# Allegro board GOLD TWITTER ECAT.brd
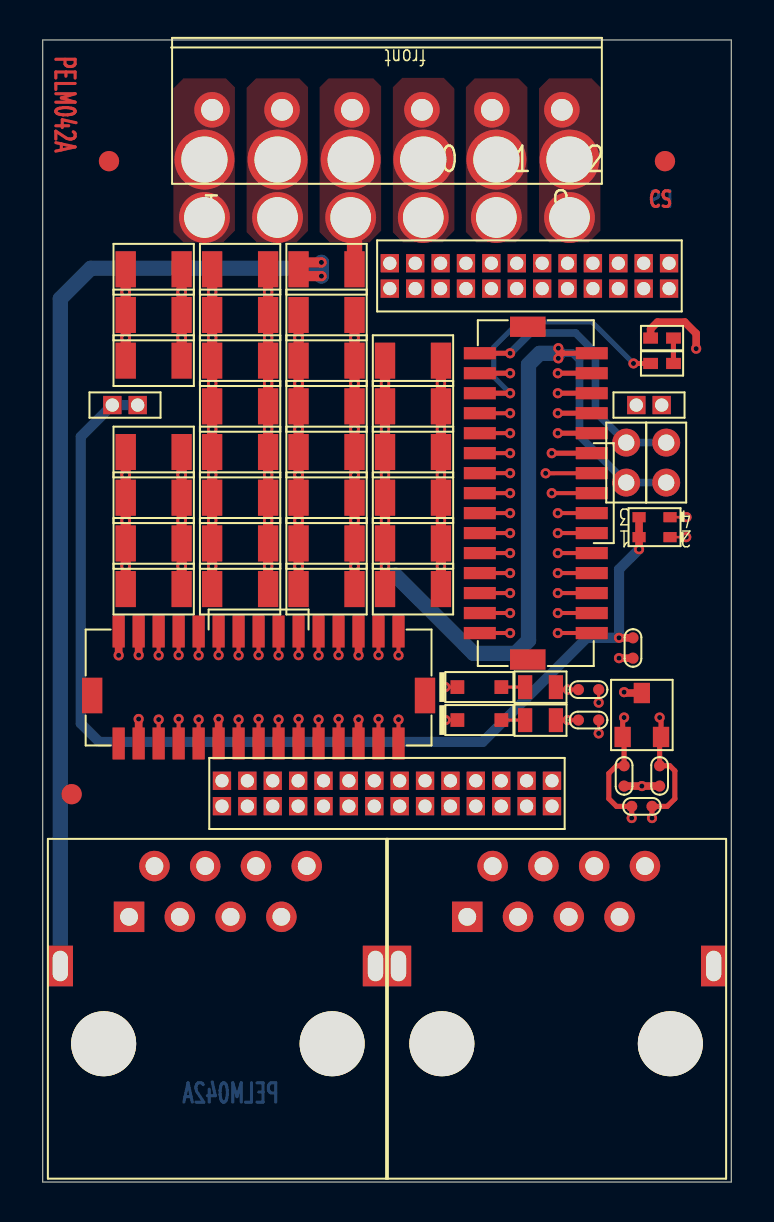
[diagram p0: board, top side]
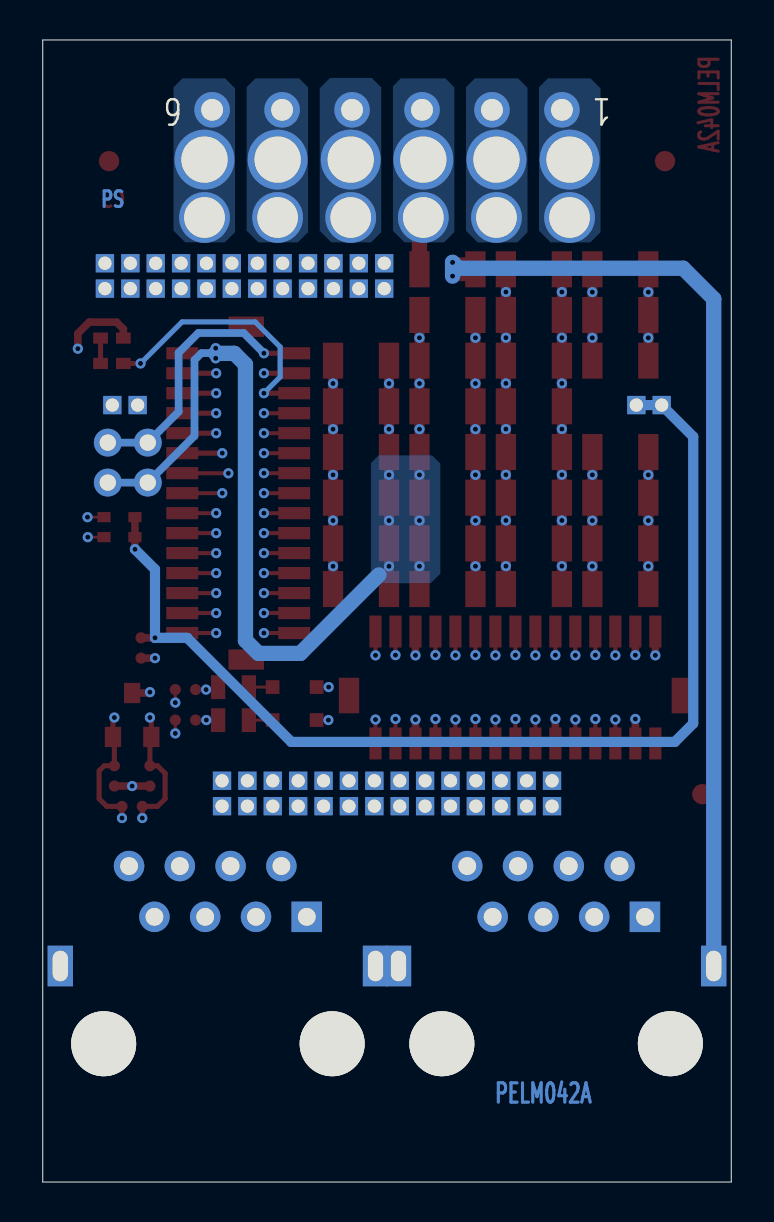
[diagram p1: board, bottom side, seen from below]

Outline 34.44 x 57.14 mm; copper layers: TOP, L2, L3, L4, L5, BOTTOM. Coordinates in mm from the lower left corner of the outline.
Outline path: 0,57.14 34.44,57.14 34.44,0 0,0 0,57.14

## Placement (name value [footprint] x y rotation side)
C1  1uF  [1206]  5.55 45.67 0 top
C2  1uF  [1206]  9.87 45.67 180 top
C4  1uF  [1206]  5.55 43.38 0 top
C5  1uF  [1206]  9.87 43.38 180 top
C6  1uF  [1206]  14.2 43.38 0 top
C7  1uF  [1206]  5.55 41.1 0 top
C8  1uF  [1206]  9.87 41.1 180 top
C9  1uF  [1206]  14.2 41.1 0 top
C10  1uF  [1206]  14.2 38.81 0 top
C11  1uF  [1206]  9.87 38.81 180 top
C12  1uF  [1206]  5.55 36.53 0 top
C13  1uF  [1206]  9.87 36.53 180 top
C14  1uF  [1206]  14.2 36.53 0 top
C15  1uF  [1206]  18.52 41.1 180 top
C16  1uF  [1206]  18.52 38.81 180 top
C17  1uF  [1206]  18.52 36.53 180 top
C18  1uF  [1206]  5.55 34.24 0 top
C19  1uF  [1206]  9.87 34.24 180 top
C20  1uF  [1206]  14.2 34.24 0 top
C21  1uF  [1206]  18.52 34.24 180 top
C22  1uF  [1206]  5.55 31.95 0 top
C23  1uF  [1206]  9.87 31.95 180 top
C24  1uF  [1206]  14.2 31.95 0 top
C25  1uF  [1206]  18.52 31.95 180 top
C26  1uF  [1206]  18.52 29.67 180 top
C27  1uF  [1206]  14.2 29.67 0 top
C28  1uF  [1206]  9.87 29.67 180 top
C29  1uF  [1206]  5.55 29.67 0 top
C32  1uF  [0402]  29.53 26.72 270 top
C33  33pF  [0402]  29.08 20.32 270 top
C34  33pF  [0402]  30.86 20.32 270 top
D1  LDR/G  [LED06]  30.61 32.77 180 top
D5  BAS521  [SOD523]  30.98 40.96 180 top
D6  BAS521  [SOD523]  30.98 42.23 0 top
D7  NUP2105L  [SOT23]  29.97 23.37 180 top
D8  DZ6.2v  [SOD323]  21.84 23.11 0 top
D9  DZ6.2v  [SOD323]  21.84 24.77 0 top
FD1  -  [FD1]  1.45 19.41 0 top
FD2  -  [FD1]  31.13 51.08 0 top
FD3  -  [FD1]  3.31 51.08 0 top
H1  H8  [H08]  8.09 48.26 0 top
H2  H8  [H08]  11.75 48.26 0 top
H3  H8  [H08]  15.41 48.26 0 top
H4  H8  [H08]  19.04 48.26 0 top
H5  H8  [H08]  22.69 48.26 0 top
H6  H8  [H08]  26.35 48.26 0 top
H7  -  [H52]  8.09 51.16 0 top
H8  -  [H52]  11.75 51.16 0 top
H9  -  [H52]  15.41 51.16 0 top
H10  -  [H52]  19.04 51.16 0 top
H11  -  [H52]  22.69 51.16 0 top
H12  -  [H52]  26.35 51.16 0 top
J2  J  [HEADER194]  31.33 45.97 270 top
J3  J  [HEADER245]  25.48 20.08 270 top
J7  J  [HEADER52A]  31.19 37 270 top
J8  J  [HEADER278A]  29.7 38.88 0 top
J9  J  [HEADER278A]  3.48 38.88 0 top
J10  J  [HEADER283]  24.67 34.47 180 top
J11  J  [HEADER283]  10.8 24.74 270 top
J12  J  [HEADER52]  29.19 37 270 top
J13  J  [CON22]  4.32 13.27 180 top
J15  J  [CON22]  21.24 13.27 180 top
J16  J  [TB54]  8.47 53.65 180 top
NOREF  -  []  0 57.14 0 top
NOREF#2  -  []  0 0 90 top
NOREF#3  -  []  -39.4 83.35 0 top
NOREF#4  -  []  0 0 90 top
NOREF#5  -  []  0 0 0 top
R12  0R  [0402]  27.3 23.11 0 top
R13  3.74K  [0603]  24.9 23.11 180 top
R14  0R  [0402]  27.3 24.64 0 top
R15  0R  [1206]  14.2 45.67 180 top
R16  Demo  [0402]  29.97 18.8 0 top
R17  3.74K  [0603]  24.9 24.76 180 top

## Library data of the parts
C1 C2 C4-C29 = C1uF_200v_X7R_1206
C32 = C1uF_10v_X5R_0402
C33 C34 = C33pF_50v_NPO_0402
D1 = LED_BICOLOR_LED06
D5 D6 = BAS521HT1_SOD523
D7 = NUP2105L_SOT23
D8 D9 = MM3Z6V2_SOD323
FD1-FD3 = FIDUCIAL1_FD1
H1-H6 = HOLE08_H08
H7-H12 = HOLE52_H52
J2 = HEADER2x12PF1.27_4.3_HEADER194
J3 = HEADER2x14PF1.27_4.3_HEADER245
J7 = HEADER52A_FP12
J8 J9 = HEADER2P1.27mmHEADER278A
J10 J11 = HEADER2x15P1mm_HEADER283
J12 = HEADER2PF2mm_4.3mm_HEADER52
J13 J15 = CON1PORT8P_CON22
J16 = TB6P3.5mm_TB54
R12 R14 = 0R_0402
R13 R17 = 3.74K1%_0603
R15 = 0R_1206
R16 = RES0402_DEMO

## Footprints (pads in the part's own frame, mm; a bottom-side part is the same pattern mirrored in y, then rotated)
0402
  round 0.559 smd: 1(-0.508,0) 2(0.508,0)
0603
  rect 0.711x1.194 smd: 1(-0.77,0) 2(0.77,0)
1206
  rect 1.016x1.803 smd: 1(-1.4,0) 2(1.4,0)
CON22
  round 3.251 hole 3.302 unplated: (-10.16,6.35) (1.27,6.35)
  rect 1.524x1.524 hole 0.889: 1(0,0)
  round 1.524 hole 0.889: 2(-1.27,-2.54) 3(-2.54,0) 4(-3.81,-2.54) 5(-5.08,0) 6(-6.35,-2.54) 7(-7.62,0) 8(-8.89,-2.54)
  rect 1.27x2.032 hole 0.762x1.524: 9(3.44,2.46) 10(-12.33,2.46)
FD1
  round 1.016 smd: 1(0,0)
H08
  round 2.54 hole 2.032: 1(0,0)
H52
  round 2.997 hole 2.311: 1(0,0)
HEADER52
  round 1.397 hole 0.813: 1(0,0) 2(2,0)
HEADER52A
  round 1.397 hole 0.813: 1(0,0) 2(2,0)
HEADER194
  rect 0.914x0.914 hole 0.66: 1(0,0) 2(1.27,0) 3(0,-1.27) 4(1.27,-1.27) 5(0,-2.54) 6(1.27,-2.54) 7(0,-3.81) 8(1.27,-3.81) 9(0,-5.08) 10(1.27,-5.08) 11(0,-6.35) 12(1.27,-6.35) 13(0,-7.62) 14(1.27,-7.62) 15(0,-8.89) 16(1.27,-8.89) 17(0,-10.16) 18(1.27,-10.16) 19(0,-11.43) 20(1.27,-11.43) 21(0,-12.7) 22(1.27,-12.7) 23(0,-13.97) 24(1.27,-13.97)
HEADER245
  rect 0.914x0.914 hole 0.66: 1(0,0) 2(1.27,0) 3(0,-1.27) 4(1.27,-1.27) 5(0,-2.54) 6(1.27,-2.54) 7(0,-3.81) 8(1.27,-3.81) 9(0,-5.08) 10(1.27,-5.08) 11(0,-6.35) 12(1.27,-6.35) 13(0,-7.62) 14(1.27,-7.62) 15(0,-8.89) 16(1.27,-8.89) 17(0,-10.16) 18(1.27,-10.16) 19(0,-11.43) 20(1.27,-11.43) 21(0,-12.7) 22(1.27,-12.7) 23(0,-13.97) 24(1.27,-13.97) 25(0,-15.24) 26(1.27,-15.24) 27(0,-16.51) 28(1.27,-16.51)
HEADER278A
  rect 0.914x0.914 hole 0.66: 1(0,0) 2(1.27,0)
HEADER283
  rect 1.778x1.016 smd: (0.4,8.325) (0.4,-8.325)
  rect 1.6x0.61 smd: 1(-2.8,7) 2(2.8,7) 3(-2.8,6) 4(2.8,6) 5(-2.8,5) 6(2.8,5) 7(-2.8,4) 8(2.8,4) 9(-2.8,3) 10(2.8,3) 11(-2.8,2) 12(2.8,2) 13(-2.8,1) 14(2.8,1) 15(-2.8,0) 16(2.8,0) 17(-2.8,-1) 18(2.8,-1) 19(-2.8,-2) 20(2.8,-2) 21(-2.8,-3) 22(2.8,-3) 23(-2.8,-4) 24(2.8,-4) 25(-2.8,-5) 26(2.8,-5) 27(-2.8,-6) 28(2.8,-6) 29(-2.8,-7) 30(2.8,-7)
LED06
  rect 0.66x0.508 smd: 1(0.775,0.5) 2(-0.775,0.5) 3(0.775,-0.5) 4(-0.775,-0.5)
SOD323
  rect 0.686x0.686 smd: 1(-1.1,0) 2(1.1,0)
SOD523
  rect 0.737x0.559 smd: 1(-0.572,0) 2(0.572,0)
SOT23
  rect 0.813x1.016 smd: 1(0.96,1.1) 2(-0.96,1.1) 3(0,-1.1)
TB54
  round 1.778 hole 1.09: 1(0,0) 2(-3.5,0) 3(-7,0) 4(-10.5,0) 5(-14,0) 6(-17.5,0)

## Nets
3.3V: C32.1 D1.1(ANODE_R) D1.3(ANODE_G) D6.1(K) J9.1 J9.2
+5VE: D5.2(A) J2.19 J10.19 J10.26
GND: C32.2 D7.3(PIN3) J2.21 J2.23 J3.7 J3.8 J3.21 J3.22 J10.21 J10.23 J10.25 J10.27 J10.28 J11.5 J11.6 J11.20 J11.27 J11.28 J11.29 J13.3 J13.7 J15.3 J15.7
GND_POWER: C33.2 C34.2 J13.6 J13.9 J13.10 J15.6 J15.9 J15.10 R15.2
ANALOG1+: J3.9 J11.7
ANALOG1-: J3.10 J11.8
AUX_H: J7.1 J10.30 J12.1
CAN_H: C33.1 D7.1(PIN1) J3.1 J13.1 J15.1 R16.1
CAN_L: C34.1 D7.2(PIN2) J3.2 J13.2 J15.2 R16.2
ENCA_A+_ABS_C+: J2.1 J10.1
ENCA_A-_ABS_C-: J2.3 J10.3
ENCA_B+_ABS_D+: J2.5 J10.5
ENCA_B-_ABS_D-: J2.7 J10.7
ENCA_INDEX+: J2.9 J10.9
ENCA_INDEX-: J2.11 J10.11
ENCB_A+: J2.4 J10.4
ENCB_A-: J2.2 J10.2
ENCB_B+: J2.8 J10.8
ENCB_B-: J2.6 J10.6
ENCB_INDEX+: J2.12 J10.12
ENCB_INDEX-: J2.10 J10.10
ENCC_A_O+: J2.16 J10.16
ENCC_A_O-: J2.14 J10.14
ENCC_B_O+: J2.20 J10.20
ENCC_B_O-: J2.18 J10.18
ENCC_INDEX_O+: J2.24 J10.24
ENCC_INDEX_O-: J2.22 J10.22
GPIO5_ANALOG_IN: J3.11 J11.9
GPIO8_PAL_RS232_RX: J3.6 J11.4
GPIO9_PAL_RS232_TX: J3.5 J11.3
HA: J2.13 J10.13
HB: J2.15 J10.15
HC: J2.17 J10.17
IN1: J3.28 J11.26
IN2: J3.27 J11.25
IN3: J3.26 J11.24
IN4: J3.25 J11.23
IN5: J3.24 J11.22
IN6: J3.23 J11.21
LED1: D1.2(CATHODE_R) J3.15 J11.13
LED2: D1.4(CATHODE_G) J3.16 J11.14
M1: H4.1(H) H10.1(H) J16.4
M2: H5.1(H) H11.1(H) J16.5
M3: H6.1(H) H12.1(H) J16.6
OUT1_E: J3.20 J11.18
OUT2_E: J3.18 J11.16
OUT3_E: J3.19 J11.17
OUT4_E: J3.17 J11.15
PE: H3.1(H) H9.1(H) J16.3 R15.1
PR: C1.2 C2.2 C4.2 C5.2 C6.2 C7.2 C8.2 C9.2 C10.2 C11.2 C12.2 C13.2 C14.2 C15.2 C16.2 C17.2 C18.2 C19.2 C20.2 C21.2 C22.2 C23.2 C24.2 C25.2 C26.2 C27.2 C28.2 C29.2 H1.1(H) H7.1(H) J7.2 J10.29 J12.2 J16.1
RS232_RX: J3.4 J11.2
RS232_TX: J3.3 J11.1
STO1: J3.12 R12.1 R13.1
STO1_IN: D8.1(K) J11.10 R12.2
STO2: J3.14 R14.1 R17.1
STO2_IN: D9.1(K) J11.12 R14.2
STO_RET: J3.13 J11.11
VP+: C1.1 C2.1 C4.1 C5.1 C6.1 C7.1 C8.1 C9.1 C10.1 C11.1 C12.1 C13.1 C14.1 C15.1 C16.1 C17.1 C18.1 C19.1 C20.1 C21.1 C22.1 C23.1 C24.1 C25.1 C26.1 C27.1 C28.1 C29.1 H2.1(H) H8.1(H) J16.2
N14985989: D5.1(K) D6.2(A)
N16792816: D8.2(A) R13.2
N16792834: D9.2(A) R17.2

Pads without a net: FD1 1; FD2 1; FD3 1; J8 1 2; J11 19 30; J13 4 5 8; J15 4 5 8

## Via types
v1: diameter 0.508, hole 0.254, TOP to BOTTOM, 127 vias

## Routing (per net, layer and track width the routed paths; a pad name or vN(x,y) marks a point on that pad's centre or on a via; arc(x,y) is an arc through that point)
3.3V: length 58.3
  TOP w0.381: v1(29.83,31.66) D1.1 D1.3 ; v1(32.69,41.7) 32.69,42.46 32.12,43.03 30.75,43.03 30.41,42.68 D6.1 ; C32.1 v1(28.83,27.23)
  BOTTOM w0.508: v1(29.83,31.66) 28.83,30.66 v1(28.83,27.23) 27.22,27.23 22.01,22.02 2.83,22.02 1.9,22.94 1.9,37.29 3.48,38.87 J9.1 J9.2
+5VE: length 15.4
  TOP w0.254: J10.19 v1(25.46,36.47) ; D5.2 v1(29.55,40.96) ; J10.26 v1(23.38,39.47)
  BOTTOM w0.254: v1(29.55,40.96) 27.48,43.03 23.82,43.03 22.57,41.78 22.57,40.28 v1(23.38,39.47)
GND: length 17.1
  TOP w0.254: J10.23 v1(25.77,38.47) ; J10.28 v1(23.38,40.47) ; J10.21 v1(25.77,37.47) ; J10.25 v1(25.77,39.47) ; J10.27 v1(25.77,40.47)
  TOP w0.381: J11.20 v1(8.8,23.17) ; J11.5 v1(15.8,26.35) ; C32.2 v1(28.83,26.21) ; J11.28 v1(4.8,23.17) ; J11.6 v1(15.8,23.14) ; J11.29 v1(3.8,26.35) ; D7.3 29.13,24.47 v1(29.08,24.51) ; J11.27 v1(4.8,26.36)
GND_POWER: length 57.6
  TOP w0.381: C33.2 v1(29.97,19.81) C34.2
  TOP w0.508: v1(13.94,46.01) 13.14,46.01 R15.2 13.14,45.33 v1(13.94,45.33)
  L4 w0.762: v1(29.97,19.81) 29.41,19.81 27.59,17.99 J15.6
  BOTTOM w0.762: J13.9 0.88,44.19 2.41,45.72 13.65,45.72 v1(13.94,46.01) v1(13.94,45.33)
ANALOG1+: length 10.1
  TOP w0.203: J11.7 v1(14.8,26.36)
  L3 w0.178: 17.3,23.86 17.3,22.89
  L3 w0.203: J3.9 20.4,20.29 18.33,22.35 17.84,22.35 17.3,22.89 ; v1(14.8,26.36) 17.3,23.86
ANALOG1-: length 9.5
  TOP w0.203: J11.8 v1(14.8,23.17)
  L4 w0.127: 19.76,20.48 19.76,19.44
  L4 w0.203: 19.76,19.44 J3.10 ; 19.76,20.48 18.85,21.39 16.14,21.39 14.8,22.72 v1(14.8,23.17)
AUX_H: length 13.7
  TOP w0.254: J10.30 v1(23.38,41.47)
  BOTTOM w0.381: J7.1 J12.1 27.65,38.54 27.65,41.49 26.66,42.48 24.39,42.48 v1(23.38,41.47)
CAN_H: length 46.3
  TOP w0.254: v1(29.46,18.21) R16.1 28.7,18.8 28.32,19.18 28.32,20.45 28.7,20.83 C33.1 29.08,22.2 D7.1 29.01,23.17 v1(29.08,23.24)
  L2 w0.254: J13.1 5.23,12.36 5.23,11.87 5.8,11.3 12.45,11.3 15.39,14.24 20.26,14.24 21.23,13.27 J15.1
  L3 w0.152: J3.1 25.97,19.58 27.43,19.58 27.71,19.85 27.71,21.1 28.43,21.83 29.59,21.83 29.85,22.09 29.85,22.94 29.54,23.24 v1(29.08,23.24)
  L3 w0.254: J15.1 21.24,16.23 22.61,17.6 28.85,17.6 v1(29.46,18.21)
CAN_L: length 47.1
  TOP w0.254: v1(30.48,18.21) R16.2 31.24,18.8 31.62,19.18 31.62,20.57 31.37,20.83 C34.1 30.86,22.2 D7.2 30.93,23.17 v1(30.86,23.24)
  L2 w0.254: J13.2 5.69,15.71 5.69,12.1 6.03,11.76 12.29,11.76 15.15,14.63 21.32,14.63 22.5,15.81 J15.2
  L3 w0.152: v1(30.86,23.24) 30.41,23.24 30.13,22.96 30.13,21.94 29.7,21.51 28.56,21.51 28,20.96 28,19.7 27.6,19.3 25.97,19.3 J3.2
  L3 w0.254: J15.2 22.51,16.72 22.96,17.17 29.44,17.17 v1(30.48,18.21)
ENCA_A+_ABS_C+: length 23.2
  TOP w0.203: J10.1 v1(25.77,27.47)
  L3 w0.127: 30.7,45.34 30.7,44.22
  L3 w0.152: 30.7,44.22 30.24,43.77 29.49,43.77 28.19,42.47 28.19,29.5 26.16,27.47 v1(25.77,27.47) ; J2.1 30.7,45.34
ENCA_A-_ABS_C-: length 21.2
  TOP w0.203: J10.3 v1(25.77,28.47)
  L3 w0.127: 29.43,44.31 29.43,45.34
  L3 w0.152: 29.43,45.34 J2.3 ; 29.43,44.31 27.85,42.73 27.85,30.15 26.16,28.47 v1(25.77,28.47)
ENCA_B+_ABS_D+: length 19.7
  TOP w0.203: J10.5 v1(25.77,29.47)
  L3 w0.127: 28.16,45.34 28.16,44.22
  L3 w0.152: J2.5 28.16,45.34 ; v1(25.77,29.47) 26.18,29.47 27.51,30.8 27.51,43.57 28.16,44.22
ENCA_B-_ABS_D-: length 18.4
  TOP w0.203: J10.7 v1(25.77,30.47)
  L3 w0.127: 26.89,45.34 26.89,44.12
  L3 w0.152: 26.89,44.12 27.18,43.83 27.18,31.46 26.18,30.47 v1(25.77,30.47) ; J2.7 26.89,45.34
ENCA_INDEX+: length 17.6
  TOP w0.203: J10.9 v1(25.77,31.47)
  L3 w0.127: 25.62,44.25 25.62,45.34
  L3 w0.152: 25.62,44.25 26.84,43.03 26.84,32.14 26.17,31.47 v1(25.77,31.47) ; 25.62,45.34 J2.9
ENCA_INDEX-: length 16.7
  TOP w0.203: J10.11 v1(25.77,32.47)
  L3 w0.127: 24.35,45.34 24.35,44.36
  L3 w0.152: 24.35,44.36 26.5,42.2 26.5,33.05 25.92,32.47 v1(25.77,32.47) ; J2.11 24.35,45.34
ENCB_A+: length 21.9
  TOP w0.203: J10.4 v1(23.38,28.47)
  L4 w0.152: v1(23.38,28.47) 23.38,28.47 23.88,28.97 26.17,28.97 27.67,30.48 27.67,42.24 30.06,44.64 J2.4
ENCB_A-: length 23.9
  TOP w0.203: J10.2 v1(23.38,27.47)
  L4 w0.152: v1(23.38,27.47) 23.88,27.96 26.15,27.96 28.02,29.84 28.02,42.03 29.46,43.47 30.45,43.47 31.33,44.36 J2.2
ENCB_B+: length 18.8
  TOP w0.203: J10.8 v1(23.38,30.47)
  L4 w0.152: v1(23.38,30.47) 23.38,30.47 23.89,30.98 26.24,30.98 27.01,31.75 27.01,44.19 J2.8
ENCB_B-: length 20.3
  TOP w0.203: J10.6 v1(23.38,29.47)
  L4 w0.152: J2.6 28.79,44.09 27.34,42.63 27.34,31.19 26.11,29.96 23.87,29.96 v1(23.38,29.47)
ENCB_INDEX+: length 16.8
  TOP w0.203: J10.12 v1(23.38,32.47)
  L4 w0.152: J2.12 24.98,44.1 26.32,42.76 26.32,33.26 26.02,32.97 23.87,32.97 23.38,32.47 v1(23.38,32.47)
ENCB_INDEX-: length 17.6
  TOP w0.203: J10.10 v1(23.38,31.47)
  L4 w0.152: v1(23.38,31.47) 23.88,31.97 26.04,31.97 26.67,32.6 26.67,43.73 26.25,44.16 J2.10
ENCC_A_O+: length 13.4
  TOP w0.203: J10.16 v1(23.38,34.47)
  L3 w0.152: v1(23.38,34.47) 23.89,34.97 23.89,35.42 24.56,36.09 24.56,37.03 24.89,37.37 24.89,42.25 J2.16
ENCC_A_O-: length 14.1
  TOP w0.203: J10.14 v1(23.38,33.47)
  L3 w0.152: J2.14 23.71,44.22 25.23,42.7 25.23,37.1 24.93,36.8 24.93,35.93 24.21,35.21 24.21,34.29 v1(23.38,33.47)
ENCC_B_O+: length 12.8
  TOP w0.203: J10.20 v1(23.38,36.47)
  L3 w0.152: J2.20 19.9,44.62 21.2,43.32 22.74,43.32 24.22,41.84 24.22,37.67 23.87,37.33 23.87,36.96 v1(23.38,36.47)
ENCC_B_O-: length 13.2
  TOP w0.203: J10.18 v1(23.38,35.47)
  L3 w0.152: J2.18 21.17,44.37 21.72,43.82 22.77,43.82 24.55,42.04 24.55,37.48 24.18,37.11 24.18,36.27 v1(23.38,35.47)
ENCC_INDEX_O+: length 11.9
  TOP w0.203: J10.24 v1(23.38,38.47)
  L3 w0.152: J2.24 18.35,43.72 19.93,43.72 20.93,42.72 22.18,42.72 22.87,42.03 22.87,38.98 v1(23.38,38.47)
ENCC_INDEX_O-: length 12.4
  TOP w0.203: J10.22 v1(23.38,37.47)
  L3 w0.152: v1(23.38,37.47) 23.89,37.98 23.89,41.65 22.5,43.04 21.05,43.04 20.08,44.01 19.33,44.01 19.19,44.14 19.19,44.14 J2.22
GPIO5_ANALOG_IN: length 9.7
  TOP w0.203: J11.9 v1(13.8,26.35)
  L3 w0.178: 16.3,22.92 16.3,23.85
  L3 w0.203: J3.11 19.13,20.09 16.3,22.92 ; 16.3,23.85 v1(13.8,26.35)
GPIO8_PAL_RS232_RX: length 9.9
  TOP w0.203: J11.4 v1(16.8,23.17)
  L4 w0.127: 22.3,19.44 22.3,20.52
  L4 w0.203: J3.6 22.3,19.44 ; 22.3,20.52 22.04,20.79 20.39,20.79 19.08,22.1 17.62,22.1 16.8,22.92 v1(16.8,23.17)
GPIO9_PAL_RS232_TX: length 10.9
  TOP w0.203: J11.3 v1(16.8,26.36)
  L3 w0.203: v1(16.8,26.36) 18.51,24.65 18.51,23.2 20.67,21.05 22.26,21.05 22.94,20.37 J3.5
HA: length 16
  TOP w0.203: J10.13 v1(25.77,33.47)
  L4 w0.127: 23.08,45.34 23.08,43.79
  L4 w0.152: v1(25.77,33.47) 25.77,33.47 25.98,33.67 25.98,36.72 25.72,36.98 25.31,36.98 25.07,37.22 25.07,41.8 23.08,43.79 ; J2.13 23.08,45.34
HB: length 15.8
  TOP w0.203: J10.15 v1(25.46,34.47)
  L4 w0.127: 21.81,44.29 21.81,45.34
  L4 w0.152: 21.81,44.29 22.09,44.01 22.32,44.01 24.72,41.61 24.72,36.29 25.02,35.98 25.46,35.98 25.66,35.78 25.66,34.71 v1(25.46,34.47) ; 21.81,45.34 J2.15
HC: length 15.6
  TOP w0.203: J10.17 v1(25.16,35.46)
  L4 w0.127: 20.54,44.3 20.54,45.34
  L4 w0.152: 20.54,44.3 21.25,43.59 22.21,43.59 24.38,41.41 24.38,36.08 25,35.46 v1(25.16,35.46) ; 20.54,45.34 J2.17
IN1: length 6.8
  TOP w0.203: J11.26 v1(5.8,23.14)
  L4 w0.127: 8.33,19.44 8.33,19.44
  L4 w0.203: v1(5.8,23.14) 5.8,21.97 8.33,19.44 ; 8.33,19.44 J3.28
IN2: length 8.8
  TOP w0.203: J11.25 v1(5.8,26.35)
  L3 w0.178: 8.3,22.64 8.3,23.85
  L3 w0.203: J3.27 8.97,21.97 8.3,22.64 ; 8.3,23.85 v1(5.8,26.35)
IN3: length 7.4
  TOP w0.203: J11.24 v1(6.8,23.17)
  L4 w0.127: 9.6,20.52 9.6,19.44
  L4 w0.203: v1(6.8,23.17) 6.8,22.6 8.43,20.97 9.15,20.97 9.6,20.52 ; 9.6,19.44 J3.26
IN4: length 8.9
  TOP w0.203: J11.23 v1(6.8,26.36)
  L3 w0.178: 9.3,22.66 9.3,23.86
  L3 w0.203: 9.3,22.66 10.24,21.72 J3.25 ; 9.3,23.86 v1(6.8,26.36)
IN5: length 7.7
  TOP w0.203: J11.22 v1(7.8,23.14)
  L4 w0.127: 10.87,20.52 10.87,19.44
  L4 w0.203: 10.87,19.44 J3.24 ; 10.87,20.52 9.71,21.68 8.59,21.68 7.8,22.48 v1(7.8,23.14)
IN6: length 9
  TOP w0.203: J11.21 v1(7.8,26.35)
  L3 w0.178: 10.3,22.86 10.3,23.85
  L3 w0.203: 10.3,22.86 11.51,21.65 J3.23 ; 10.3,23.85 v1(7.8,26.35)
LED1: length 33.5
  TOP w0.127: D1.2 v1(32.19,32.27)
  TOP w0.203: J11.13 v1(11.8,26.35)
  L2 w0.152: v1(32.19,32.27) 32.19,31.85 26.84,26.5 20.27,26.5 18.63,24.86 18.63,21.47 18.4,21.24 17.35,21.24 16.92,20.81 16.92,20.41 16.59,20.08 J3.15
  L3 w0.178: 14.3,22.21 14.3,23.85
  L3 w0.203: 14.3,22.21 16.44,20.08 J3.15 ; 14.3,23.85 v1(11.8,26.35)
LED2: length 35.3
  TOP w0.127: D1.4 v1(32.21,33.27)
  TOP w0.203: J11.14 v1(11.8,23.14)
  L2 w0.127: 17.22,20.62 17.22,19.44
  L2 w0.152: 17.22,20.62 17.55,20.95 18.63,20.95 18.93,21.25 18.93,24.66 20.47,26.2 26.97,26.2 30.6,29.82 30.6,29.83 32.75,31.97 32.75,32.73 v1(32.21,33.27) ; 17.22,19.44 J3.16
  L4 w0.127: 15.95,21.02 15.95,19.44
  L4 w0.203: 15.95,21.02 14.58,22.4 12.54,22.4 v1(11.8,23.14) ; 15.95,19.44 J3.16
Net_10: length 1.2
  TOP w0.203: 8.8,27.54 v1(8.8,26.36)
OUT1_E: length 8.1
  TOP w0.203: J11.18 v1(9.8,23.14)
  L4 w0.127: 13.41,19.44 13.41,20.45
  L4 w0.203: v1(9.8,23.14) 9.8,22.76 11.53,21.03 12.83,21.03 13.41,20.45 ; J3.20 13.41,19.44
OUT2_E: length 8.3
  TOP w0.203: J11.16 v1(10.8,23.17)
  L4 w0.127: 14.68,19.44 14.68,20.47
  L4 w0.203: v1(10.8,23.17) 10.8,22.88 11.94,21.74 13.41,21.74 14.68,20.47 ; J3.18 14.68,19.44
OUT3_E: length 9.5
  TOP w0.203: J11.17 v1(9.8,26.35)
  L3 w0.178: 11.3,23.44 11.3,22.82
  L3 w0.203: 11.3,23.44 11.3,24.85 v1(9.8,26.35) ; J3.19 14.05,20.52 13.19,21.38 12.75,21.38 11.3,22.82
OUT4_E: length 9.3
  TOP w0.203: J11.15 v1(10.8,26.36)
  L3 w0.178: 13.3,22.95 13.3,23.52
  L3 w0.203: 13.3,22.95 13.3,22.24 15.32,20.22 J3.17 ; 13.3,23.52 13.3,23.86 v1(10.8,26.36)
PE: length 2.7
  TOP w0.762: H3.1 15.6,48.07 R15.1
PR: length 90.6
  TOP w0.254: 26.05,41.47 v1(25.79,41.21) v1(25.79,41.72) 26.05,41.47 ; 26.05,41.47 J10.29
  TOP w0.508: C27.2 v1(15.6,30.81) C24.2 v1(15.6,33.1) C20.2 v1(15.6,35.38) C14.2 v1(15.6,37.67) C10.2 v1(15.6,39.95) C9.2 v1(15.6,42.24) C6.2 ; C26.2 v1(17.12,30.81) C25.2 v1(17.12,33.1) C21.2 v1(17.12,35.38) C17.2 v1(17.12,37.67) C16.2 v1(17.12,39.95) C15.2 ; C28.2 v1(8.47,30.82) C23.2 v1(8.47,33.1) C19.2 v1(8.47,35.39) C13.2 v1(8.47,37.67) C11.2 v1(8.47,39.96) C8.2 v1(8.47,42.25) C5.2 v1(8.47,44.53) C2.2 ; C7.2 v1(6.95,42.24) C4.2 v1(6.95,44.53) C1.2 ; C29.2 v1(6.95,30.81) C22.2 v1(6.95,33.1) C18.2 v1(6.95,35.38) C12.2
  BOTTOM w0.381: 26.05,41.47 v1(25.79,41.21) v1(25.79,41.72) 26.04,41.47 26.05,41.47 ; 26.05,41.47 26.51,41.47 26.85,41.13 26.85,37.33 J12.2 J7.2
  BOTTOM w0.762: 17.63,30.38 21.56,26.45 23.65,26.45 24.3,27.1 24.3,40.9 24.86,41.46 25.79,41.46
RS232_RX: length 10
  TOP w0.203: J11.2 v1(17.8,23.14)
  L4 w0.127: 23.57,20.43 23.57,19.44
  L4 w0.203: 23.57,19.44 J3.4 ; 23.57,20.43 22.69,21.31 20.79,21.31 18.96,23.14 v1(17.8,23.14)
RS232_TX: length 11.3
  TOP w0.203: J11.1 v1(17.8,26.35)
  L3 w0.203: v1(17.8,26.35) 19.01,25.14 19.01,23.52 20.96,21.57 22.99,21.57 24.21,20.35 J3.3
STO1: length 14.1
  TOP w0.152: R13.1 25.68,23.11 v1(26.26,23.11) R12.1
  L4 w0.152: v1(26.26,23.11) 26.84,22.53 26.84,19.08 25.86,18.09 19.37,18.09 19.13,18.34 J3.12
STO1_IN: length 17.4
  TOP w0.152: D8.1 v1(20.16,23.11) ; R12.2 v1(27.81,22.45)
  TOP w0.203: J11.10 v1(13.8,23.14)
  L3 w0.152: v1(27.81,22.45) 24.56,22.45 23.89,23.11 v1(20.16,23.11)
  L4 w0.152: v1(13.8,23.14) 13.8,23.14 14.54,23.88 19.39,23.88 v1(20.16,23.11)
STO2: length 17.8
  TOP w0.152: R17.1 25.79,24.64 v1(26.27,24.64) R14.1
  L4 w0.152: J3.14 17.86,18.1 18.15,17.81 25.99,17.81 27.15,18.97 27.15,23.76 v1(26.27,24.64)
STO2_IN: length 18.5
  TOP w0.152: D9.1 v1(20.14,24.77) ; R14.2 v1(27.81,23.99)
  TOP w0.203: J11.12 v1(12.8,23.17)
  L3 w0.152: v1(27.81,23.99) 24.84,23.99 24.07,24.77 v1(20.14,24.77)
  L4 w0.152: v1(12.8,23.17) 12.8,23.17 13.81,24.17 19.55,24.17 v1(20.14,24.77)
STO_RET: length 9.6
  TOP w0.203: J11.11 v1(12.8,26.36)
  L3 w0.178: 15.3,22.64 15.3,23.87
  L3 w0.203: J3.13 15.3,22.64 ; 15.3,23.87 v1(12.8,26.36)
VP+: length 52.6
  TOP w0.508: C1.1 v1(4.15,44.53) C4.1 v1(4.15,42.24) C7.1 ; C29.1 v1(4.15,30.81) C22.1 v1(4.15,33.1) C18.1 v1(4.15,35.38) C12.1 ; C2.1 v1(11.27,44.53) C5.1 v1(11.27,42.25) C8.1 v1(11.27,39.96) C11.1 v1(11.27,37.67) C13.1 v1(11.27,35.39) C19.1 v1(11.27,33.1) C23.1 v1(11.27,30.82) C28.1 ; C26.1 v1(19.92,30.81) C25.1 v1(19.92,33.1) C21.1 v1(19.92,35.38) C17.1 v1(19.92,37.67) C16.1 v1(19.92,39.95) C15.1 ; C6.1 v1(12.8,42.24) C9.1 v1(12.8,39.95) C10.1 v1(12.8,37.67) C14.1 v1(12.8,35.38) C20.1 v1(12.8,33.1) C24.1 v1(12.8,30.81) C27.1
N14985989: length 1.3
  TOP w0.254: D6.2 D5.1
N16792816: length 1.2
  TOP w0.152: D8.2 24.13,23.11 R13.2
N16792834: length 1.2
  TOP w0.152: R17.2 24.13,24.77 D9.2

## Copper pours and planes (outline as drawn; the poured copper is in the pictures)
3.3V on L2: 28.65,26.76 28.39,27.02 28.39,27.83 28.4,27.84 28.57,27.67 28.57,39.4 29.26,40.09 29.96,40.09 30.34,40.47 30.34,41.82 30.66,42.13 32.98,42.13 33.73,41.38 33.73,27.27 33.22,26.76
+5VE on L2: 20.98,27.37 20.98,41.46 19.57,42.86 17.05,42.86 16.58,43.32 16.58,46.29 16.76,46.46 32.01,46.46 33.69,44.78 33.69,43.08 33.13,42.52 30.58,42.52 30.06,41.99 30.06,40.59 29.83,40.36 29.28,40.36 29.27,40.38 29.1,40.38 28.32,39.6 28.32,28.4 26.69,26.77 21.58,26.77 ; 1 cut-out
GND on L2: 19.45,28.14 3.42,28.14 2.61,27.33 2.61,17.85 3.35,17.1 13.9,17.1 15.24,15.77 20.88,15.77 22.15,17.04 33.21,17.04 33.74,17.57 33.74,25.86 33.18,26.42 27.93,26.42 27.3,25.78 20.69,25.78 19.5,24.59 19.5,20.7 18.14,20.7 17.83,20.4 17.83,18.8 17.29,18.26 16.04,18.26 16.04,20.91 18.32,23.19 18.32,25.05 19.42,26.15 19.46,26.15 19.99,26.68 19.99,27.6
GND on L5: 4.91,10.68 2.61,12.97 2.61,27.33 3.43,28.15 20.43,28.15 20.98,28.7 20.98,41.45 19.57,42.86 17.04,42.86 16.58,43.32 16.58,43.9 16.58,46.3 16.74,46.46 32.03,46.46 33.73,44.75 33.73,14.46 31.02,11.75 19.55,11.75 18.92,12.38 15.58,12.38 13.88,10.68 ; 2 cut-outs
GND_POWER on L4: 33.98,16.05 33.98,0.78 33.64,0.44 0.86,0.44 0.44,0.86 0.44,16.29 1.3,17.14 32.89,17.14
M1 on TOP, BOTTOM, L2, L3, L4, L5: 17.51,47.52 17.51,54.78 17.98,55.24 20.07,55.24 20.59,54.72 20.59,47.6 20,47.02 18.02,47.02
M2 on TOP, BOTTOM, L2, L3, L4, L5: 21.17,47.52 21.17,54.78 21.62,55.22 23.8,55.22 24.24,54.78 24.24,47.6 23.66,47.02 21.68,47.02
M3 on TOP, BOTTOM, L2, L3, L4, L5: 24.83,47.52 24.83,54.72 25.32,55.22 27.46,55.22 27.9,54.78 27.9,47.6 27.32,47.02 25.34,47.02
PE on TOP, BOTTOM, L2, L3, L4, L5: 13.86,47.52 13.86,54.78 14.3,55.22 16.54,55.22 16.93,54.83 16.93,47.6 16.34,47.02 14.36,47.02
PR on TOP, BOTTOM, L3, L5: 6.54,47.52 6.54,54.72 7.04,55.22 9.17,55.22 9.61,54.78 9.61,47.6 9.03,47.02 7.05,47.02
PR on BOTTOM: 14.55,30.44 14.55,35.94 14.97,36.36 17.66,36.36 17.66,36.34 18.03,35.97 18.03,29.98 18.01,29.96 15.03,29.96
PR on L2: 3.72,28.75 3.52,28.94 3.52,37.8 3.8,38.07 5.96,38.07 6.21,38.33 6.21,39.5 5.98,39.73 3.75,39.73 3.52,39.95 3.52,46.79 3.64,46.92 5.83,46.92 6.54,47.63 6.54,54.72 7.04,55.22 9.17,55.22 9.61,54.78 9.61,47.62 10.55,46.69 11.72,46.69 11.91,46.49 11.91,44.84 12.31,44.45 15.94,44.45 16.13,44.26 16.13,42.91 16.65,42.39 19.29,42.39 20.51,41.17 20.51,40.18 19.29,39.95 20.51,39.73 20.51,37.89 19.29,37.67 20.51,37.44 20.51,35.61 19.29,35.38 20.51,35.16 20.51,33.32 19.29,33.1 20.51,32.87 20.51,31.04 19.29,30.81 20.51,30.58 20.51,28.84 20.42,28.75 ; 18 cut-outs
PR on L4: 3.72,28.74 3.52,28.94 3.52,37.8 3.8,38.07 5.96,38.07 6.21,38.33 6.21,39.5 5.98,39.73 3.75,39.73 3.52,39.95 3.52,46.79 3.64,46.92 5.83,46.92 6.54,47.63 6.54,54.72 7.04,55.22 9.17,55.22 9.61,54.78 9.61,47.62 10.55,46.69 11.72,46.69 11.91,46.49 11.91,44.84 12.31,44.45 15.94,44.45 16.13,44.26 16.13,42.91 16.65,42.39 19.29,42.39 20.51,41.17 20.51,28.84 20.41,28.74
VP+ on TOP, BOTTOM, L2, L4: 10.2,47.52 10.2,54.75 10.67,55.22 12.83,55.22 13.27,54.78 13.27,47.6 12.69,47.02 10.71,47.02
VP+ on L3: 20.41,28.74 3.72,28.74 3.52,28.94 3.52,37.8 3.8,38.07 5.96,38.07 6.21,38.33 6.21,39.5 5.98,39.73 3.75,39.73 3.52,39.95 3.52,46.79 3.66,46.93 6.62,46.93 6.88,46.66 9.19,46.66 10.2,47.66 10.2,54.75 10.67,55.22 12.83,55.22 13.27,54.78 13.27,45.11 13.93,44.45 15.94,44.45 16.13,44.26 16.13,42.91 16.65,42.39 19.29,42.39 20.51,41.17 20.51,28.84 ; 23 cut-outs
VP+ on L5: 3.52,28.93 3.52,37.8 3.8,38.07 5.96,38.07 6.21,38.33 6.21,39.5 5.98,39.73 3.75,39.73 3.52,39.95 3.52,46.79 3.66,46.93 6.62,46.93 6.88,46.66 9.19,46.66 10.2,47.66 10.2,54.75 10.67,55.22 12.83,55.22 13.27,54.78 13.27,45.11 13.93,44.45 15.95,44.44 16.13,44.26 16.13,42.91 16.65,42.39 19.29,42.39 20.51,41.17 20.51,28.8 20.45,28.74 3.71,28.74 ; 23 cut-outs

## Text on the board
BOTTOM: PS | PELM042A | LAYER NO.6 BOTTOM
Ref Des/Assembly Bottom: ASSEMBLY P.S.
Board Geometry/Soldermask Bottom: SOLDERMASK P.S.
Package Geometry/Pastemask Bottom: PASTEMASK P.S.
Ref Des/Silkscreen Bottom: SILKSCREEN P.S.
TOP: CS | PELM042A | LAYER NO.1 TOP
Ref Des/Assembly Top: ASSEMBLY C.S.
Board Geometry/Soldermask Top: SOLDERMASK C.S.
Package Geometry/Pastemask Top: PASTEMASK C.S.
Ref Des/Silkscreen Top: SILKSCREEN C.S.
L2: LAYER NO.2 L2
L3: LAYER NO.3 L3
L4: LAYER NO.4 L4
L5: LAYER NO.5 L5
User.7: FIGURE | SIZE | 10.0 | 26.0 | 32.0 | 35.0 | 42.9 | 80.0 | 91.0 | 130.0 | 60.0x30.0 | DRILL CHART: TOP to BOTTOM | ALL UNITS ARE IN MILS | TOLERANCE | +4.0/-2.0 | +2.0/-2.0 | +4.0/-0.0 | PLATED | NON-PLATED | QTY | 127 | 56 | 4 | 16 | 6
User.14: DRILL
